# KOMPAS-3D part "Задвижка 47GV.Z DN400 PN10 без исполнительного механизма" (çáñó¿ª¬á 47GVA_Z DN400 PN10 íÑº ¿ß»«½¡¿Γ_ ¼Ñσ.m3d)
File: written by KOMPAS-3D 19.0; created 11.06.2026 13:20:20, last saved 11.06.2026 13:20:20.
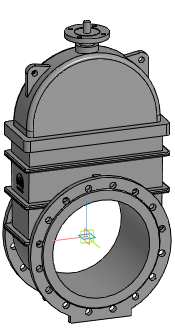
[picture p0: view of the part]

Document properties: Автор: Евгений; Полное имя файла: Z:\3.Личные\kachalov\001_3d для проектировщиков\2.2 Тип 47GVA, 47GVA.Z\_stp\_stp_Задвижка 47GVA.Z DN350-DN1200 без исп.мех\Задвижка 47GVA_Z DN400 PN10 без исполнит_ мех.m3d

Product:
- Part/product: Задвижка 47GV.Z DN400 PN10 без исполнительного механизма

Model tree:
1. Операция без истории:1  (labels: Задвижка 47GV.Z DN400 PN10 без исполнительного механизма)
